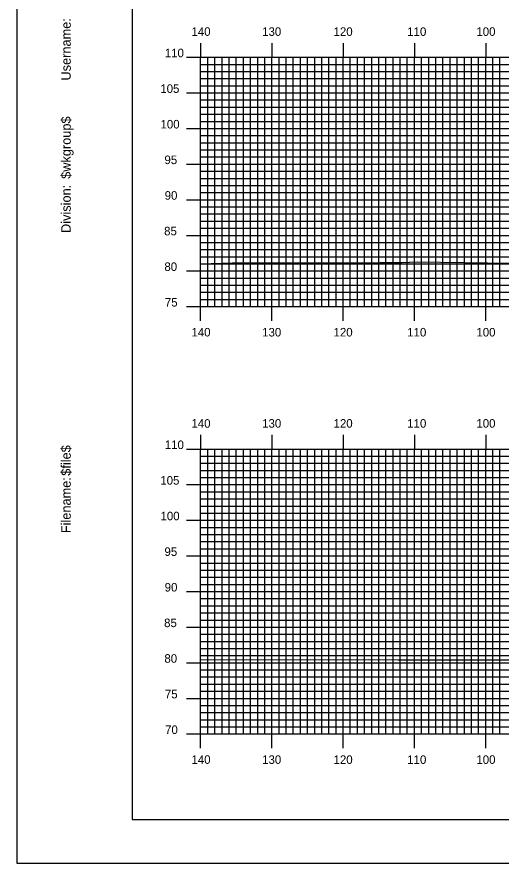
# Model space of a CAD drawing. Extents: x 1759430 to 1759773, y 442591 to 442811.
# Drawn here: x 1759429.9 to 1759497.8, y 442590.5 to 442709.3 of the extents above; entities that cross this region are included whole.
import ezdxf

# ---------------------------------------------------------------- set-up
doc = ezdxf.new("R2010")
doc.units = 0
for name, color, linetype in [('BORDER', 7, 'Continuous'), ('H_V ANNOTATION', 7, 'Continuous'), ('MAJOR', 7, 'Continuous'), ('MINOR', 7, 'Continuous'), ('PLOT BOUNDARY', 7, 'Continuous'), ('S_Roadway_Centerline', 7, 'Continuous')]:
    doc.layers.add(name, color=color, linetype=linetype)

msp = doc.modelspace()

# ---------------------------------------------------------------- linework, layer by layer
at = {"layer": 'BORDER'}
msp.add_lwpolyline([(1759446.07, 442596.67), (1759766.07, 442596.67), (1759766.07, 442806.67), (1759446.07, 442806.67)], close=True, dxfattribs=at)
at = {"layer": 'MAJOR'}
for p, q in [((1759455.67, 442705.67), (1759455.67, 442703.67)), ((1759465.67, 442705.67), (1759465.67, 442703.67)), ((1759475.67, 442705.67), (1759475.67, 442703.67)), ((1759485.67, 442705.67), (1759485.67, 442703.67)), ((1759495.67, 442705.67), (1759495.67, 442703.67)), ((1759453.67, 442703.67), (1759455.67, 442703.67)), ((1759455.67, 442703.67), (1759735.67, 442703.67)), ((1759455.67, 442668.67), (1759455.67, 442703.67)), ((1759455.67, 442668.67), (1759455.67, 442703.67)), ((1759455.67, 442703.67), (1759735.67, 442703.67)), ((1759465.67, 442668.67), (1759465.67, 442703.67)), ((1759475.67, 442668.67), (1759475.67, 442703.67)), ((1759485.67, 442668.67), (1759485.67, 442703.67)), ((1759495.67, 442668.67), (1759495.67, 442703.67)), ((1759453.67, 442698.67), (1759455.67, 442698.67)), ((1759455.67, 442698.67), (1759735.67, 442698.67)), ((1759453.67, 442693.67), (1759455.67, 442693.67)), ((1759455.67, 442693.67), (1759735.67, 442693.67)), ((1759453.67, 442688.67), (1759455.67, 442688.67)), ((1759455.67, 442688.67), (1759735.67, 442688.67)), ((1759453.67, 442683.67), (1759455.67, 442683.67)), ((1759455.67, 442683.67), (1759735.67, 442683.67)), ((1759453.67, 442678.67), (1759455.67, 442678.67)), ((1759455.67, 442678.67), (1759735.67, 442678.67)), ((1759453.67, 442673.67), (1759455.67, 442673.67)), ((1759455.67, 442673.67), (1759735.67, 442673.67)), ((1759453.67, 442668.67), (1759455.67, 442668.67)), ((1759455.67, 442668.67), (1759735.67, 442668.67)), ((1759455.67, 442668.67), (1759735.67, 442668.67)), ((1759455.67, 442666.66), (1759455.67, 442668.67)), ((1759465.67, 442666.66), (1759465.67, 442668.67)), ((1759475.67, 442666.66), (1759475.67, 442668.67)), ((1759485.67, 442666.66), (1759485.67, 442668.67)), ((1759495.67, 442666.66), (1759495.67, 442668.67)), ((1759455.67, 442650.67), (1759455.67, 442648.67)), ((1759465.67, 442650.67), (1759465.67, 442648.67)), ((1759475.67, 442650.67), (1759475.67, 442648.67)), ((1759485.67, 442650.67), (1759485.67, 442648.67)), ((1759495.67, 442650.67), (1759495.67, 442648.67)), ((1759453.67, 442648.67), (1759455.67, 442648.67)), ((1759455.67, 442648.67), (1759735.67, 442648.67)), ((1759455.67, 442608.67), (1759455.67, 442648.67)), ((1759455.67, 442608.67), (1759455.67, 442648.67)), ((1759455.67, 442648.67), (1759735.67, 442648.67)), ((1759465.67, 442608.67), (1759465.67, 442648.67)), ((1759475.67, 442608.67), (1759475.67, 442648.67)), ((1759485.67, 442608.67), (1759485.67, 442648.67)), ((1759495.67, 442608.67), (1759495.67, 442648.67)), ((1759453.67, 442643.67), (1759455.67, 442643.67)), ((1759455.67, 442643.67), (1759735.67, 442643.67)), ((1759453.67, 442638.67), (1759455.67, 442638.67)), ((1759455.67, 442638.67), (1759735.67, 442638.67)), ((1759453.67, 442633.67), (1759455.67, 442633.67)), ((1759455.67, 442633.67), (1759735.67, 442633.67)), ((1759453.67, 442628.67), (1759455.67, 442628.67)), ((1759455.67, 442628.67), (1759735.67, 442628.67)), ((1759453.67, 442623.67), (1759455.67, 442623.67)), ((1759455.67, 442623.67), (1759735.67, 442623.67)), ((1759453.67, 442618.67), (1759455.67, 442618.67)), ((1759455.67, 442618.67), (1759735.67, 442618.67)), ((1759453.67, 442613.67), (1759455.67, 442613.67)), ((1759455.67, 442613.67), (1759735.67, 442613.67)), ((1759453.67, 442608.67), (1759455.67, 442608.67)), ((1759455.67, 442608.67), (1759735.67, 442608.67)), ((1759455.67, 442608.67), (1759735.67, 442608.67)), ((1759455.67, 442606.66), (1759455.67, 442608.67)), ((1759465.67, 442606.66), (1759465.67, 442608.67)), ((1759475.67, 442606.66), (1759475.67, 442608.67)), ((1759485.67, 442606.66), (1759485.67, 442608.67)), ((1759495.67, 442606.66), (1759495.67, 442608.67))]:
    msp.add_line(p, q, dxfattribs=at)
at = {"layer": 'MINOR'}
for p, q in [((1759455.67, 442702.67), (1759735.67, 442702.67)), ((1759455.67, 442702.67), (1759457.68, 442702.67)), ((1759456.67, 442668.67), (1759456.67, 442703.67)), ((1759457.67, 442668.67), (1759457.67, 442703.67)), ((1759458.67, 442668.67), (1759458.67, 442703.67)), ((1759459.67, 442668.67), (1759459.67, 442703.67)), ((1759460.67, 442668.67), (1759460.67, 442703.67)), ((1759461.67, 442668.67), (1759461.67, 442703.67)), ((1759462.67, 442668.67), (1759462.67, 442703.67)), ((1759463.67, 442668.67), (1759463.67, 442703.67)), ((1759464.67, 442668.67), (1759464.67, 442703.67)), ((1759466.67, 442668.67), (1759466.67, 442703.67)), ((1759467.67, 442668.67), (1759467.67, 442703.67)), ((1759468.67, 442668.67), (1759468.67, 442703.67)), ((1759469.67, 442668.67), (1759469.67, 442703.67)), ((1759470.67, 442668.67), (1759470.67, 442703.67)), ((1759471.67, 442668.67), (1759471.67, 442703.67)), ((1759472.67, 442668.67), (1759472.67, 442703.67)), ((1759473.67, 442668.67), (1759473.67, 442703.67)), ((1759474.67, 442668.67), (1759474.67, 442703.67)), ((1759476.67, 442668.67), (1759476.67, 442703.67)), ((1759477.67, 442668.67), (1759477.67, 442703.67)), ((1759478.67, 442668.67), (1759478.67, 442703.67)), ((1759479.67, 442668.67), (1759479.67, 442703.67)), ((1759480.67, 442668.67), (1759480.67, 442703.67)), ((1759481.67, 442668.67), (1759481.67, 442703.67)), ((1759482.67, 442668.67), (1759482.67, 442703.67)), ((1759483.67, 442668.67), (1759483.67, 442703.67)), ((1759484.67, 442668.67), (1759484.67, 442703.67)), ((1759486.67, 442668.67), (1759486.67, 442703.67)), ((1759487.67, 442668.67), (1759487.67, 442703.67)), ((1759488.67, 442668.67), (1759488.67, 442703.67)), ((1759489.67, 442668.67), (1759489.67, 442703.67)), ((1759490.67, 442668.67), (1759490.67, 442703.67)), ((1759491.67, 442668.67), (1759491.67, 442703.67)), ((1759492.67, 442668.67), (1759492.67, 442703.67)), ((1759493.67, 442668.67), (1759493.67, 442703.67)), ((1759494.67, 442668.67), (1759494.67, 442703.67)), ((1759496.67, 442668.67), (1759496.67, 442703.67)), ((1759497.67, 442668.67), (1759497.67, 442703.67)), ((1759455.67, 442701.67), (1759735.67, 442701.67)), ((1759455.67, 442701.67), (1759457.68, 442701.67)), ((1759455.67, 442700.67), (1759735.67, 442700.67)), ((1759455.67, 442700.67), (1759457.68, 442700.67)), ((1759455.67, 442699.67), (1759735.67, 442699.67)), ((1759455.67, 442699.67), (1759457.68, 442699.67)), ((1759455.67, 442697.67), (1759735.67, 442697.67)), ((1759455.67, 442697.67), (1759457.68, 442697.67)), ((1759455.67, 442696.67), (1759735.67, 442696.67)), ((1759455.67, 442696.67), (1759457.68, 442696.67)), ((1759455.67, 442695.67), (1759735.67, 442695.67)), ((1759455.67, 442695.67), (1759457.68, 442695.67)), ((1759455.67, 442694.67), (1759735.67, 442694.67)), ((1759455.67, 442694.67), (1759457.68, 442694.67)), ((1759455.67, 442692.67), (1759735.67, 442692.67)), ((1759455.67, 442692.67), (1759457.68, 442692.67)), ((1759455.67, 442691.67), (1759735.67, 442691.67)), ((1759455.67, 442691.67), (1759457.68, 442691.67)), ((1759455.67, 442690.67), (1759735.67, 442690.67)), ((1759455.67, 442690.67), (1759457.68, 442690.67)), ((1759455.67, 442689.67), (1759735.67, 442689.67)), ((1759455.67, 442689.67), (1759457.68, 442689.67)), ((1759455.67, 442687.67), (1759735.67, 442687.67)), ((1759455.67, 442687.67), (1759457.68, 442687.67)), ((1759455.67, 442686.67), (1759735.67, 442686.67)), ((1759455.67, 442686.67), (1759457.68, 442686.67)), ((1759455.67, 442685.67), (1759735.67, 442685.67)), ((1759455.67, 442685.67), (1759457.68, 442685.67)), ((1759455.67, 442684.67), (1759735.67, 442684.67)), ((1759455.67, 442684.67), (1759457.68, 442684.67)), ((1759455.67, 442682.67), (1759735.67, 442682.67)), ((1759455.67, 442682.67), (1759457.68, 442682.67)), ((1759455.67, 442681.67), (1759735.67, 442681.67)), ((1759455.67, 442681.67), (1759457.68, 442681.67)), ((1759455.67, 442680.67), (1759735.67, 442680.67)), ((1759455.67, 442680.67), (1759457.68, 442680.67)), ((1759455.67, 442679.67), (1759735.67, 442679.67)), ((1759455.67, 442679.67), (1759457.68, 442679.67)), ((1759455.67, 442677.67), (1759735.67, 442677.67)), ((1759455.67, 442677.67), (1759457.68, 442677.67)), ((1759455.67, 442676.67), (1759735.67, 442676.67)), ((1759455.67, 442676.67), (1759457.68, 442676.67)), ((1759455.67, 442675.67), (1759735.67, 442675.67)), ((1759455.67, 442675.67), (1759457.68, 442675.67)), ((1759455.67, 442674.67), (1759735.67, 442674.67)), ((1759455.67, 442674.67), (1759457.68, 442674.67)), ((1759455.67, 442672.67), (1759735.67, 442672.67)), ((1759455.67, 442672.67), (1759457.68, 442672.67)), ((1759455.67, 442671.67), (1759735.67, 442671.67)), ((1759455.67, 442671.67), (1759457.68, 442671.67)), ((1759455.67, 442670.67), (1759735.67, 442670.67)), ((1759455.67, 442670.67), (1759457.68, 442670.67)), ((1759455.67, 442669.67), (1759735.67, 442669.67)), ((1759455.67, 442669.67), (1759457.68, 442669.67)), ((1759456.67, 442608.67), (1759456.67, 442648.67)), ((1759457.67, 442608.67), (1759457.67, 442648.67)), ((1759458.67, 442608.67), (1759458.67, 442648.67)), ((1759459.67, 442608.67), (1759459.67, 442648.67)), ((1759460.67, 442608.67), (1759460.67, 442648.67)), ((1759461.67, 442608.67), (1759461.67, 442648.67)), ((1759462.67, 442608.67), (1759462.67, 442648.67)), ((1759463.67, 442608.67), (1759463.67, 442648.67)), ((1759464.67, 442608.67), (1759464.67, 442648.67)), ((1759466.67, 442608.67), (1759466.67, 442648.67)), ((1759467.67, 442608.67), (1759467.67, 442648.67)), ((1759468.67, 442608.67), (1759468.67, 442648.67)), ((1759469.67, 442608.67), (1759469.67, 442648.67)), ((1759470.67, 442608.67), (1759470.67, 442648.67)), ((1759471.67, 442608.67), (1759471.67, 442648.67)), ((1759472.67, 442608.67), (1759472.67, 442648.67)), ((1759473.67, 442608.67), (1759473.67, 442648.67)), ((1759474.67, 442608.67), (1759474.67, 442648.67)), ((1759476.67, 442608.67), (1759476.67, 442648.67)), ((1759477.67, 442608.67), (1759477.67, 442648.67)), ((1759478.67, 442608.67), (1759478.67, 442648.67)), ((1759479.67, 442608.67), (1759479.67, 442648.67)), ((1759480.67, 442608.67), (1759480.67, 442648.67)), ((1759481.67, 442608.67), (1759481.67, 442648.67)), ((1759482.67, 442608.67), (1759482.67, 442648.67)), ((1759483.67, 442608.67), (1759483.67, 442648.67)), ((1759484.67, 442608.67), (1759484.67, 442648.67)), ((1759486.67, 442608.67), (1759486.67, 442648.67)), ((1759487.67, 442608.67), (1759487.67, 442648.67)), ((1759488.67, 442608.67), (1759488.67, 442648.67)), ((1759489.67, 442608.67), (1759489.67, 442648.67)), ((1759490.67, 442608.67), (1759490.67, 442648.67)), ((1759491.67, 442608.67), (1759491.67, 442648.67)), ((1759492.67, 442608.67), (1759492.67, 442648.67)), ((1759493.67, 442608.67), (1759493.67, 442648.67)), ((1759494.67, 442608.67), (1759494.67, 442648.67)), ((1759496.67, 442608.67), (1759496.67, 442648.67)), ((1759497.67, 442608.67), (1759497.67, 442648.67)), ((1759455.67, 442647.67), (1759735.67, 442647.67)), ((1759455.67, 442647.67), (1759457.68, 442647.67)), ((1759455.67, 442646.67), (1759735.67, 442646.67)), ((1759455.67, 442646.67), (1759457.68, 442646.67)), ((1759455.67, 442645.67), (1759735.67, 442645.67)), ((1759455.67, 442645.67), (1759457.68, 442645.67)), ((1759455.67, 442644.67), (1759735.67, 442644.67)), ((1759455.67, 442644.67), (1759457.68, 442644.67)), ((1759455.67, 442642.67), (1759735.67, 442642.67)), ((1759455.67, 442642.67), (1759457.68, 442642.67)), ((1759455.67, 442641.67), (1759735.67, 442641.67)), ((1759455.67, 442641.67), (1759457.68, 442641.67)), ((1759455.67, 442640.67), (1759735.67, 442640.67)), ((1759455.67, 442640.67), (1759457.68, 442640.67)), ((1759455.67, 442639.67), (1759735.67, 442639.67)), ((1759455.67, 442639.67), (1759457.68, 442639.67)), ((1759455.67, 442637.67), (1759735.67, 442637.67)), ((1759455.67, 442637.67), (1759457.68, 442637.67)), ((1759455.67, 442636.67), (1759735.67, 442636.67)), ((1759455.67, 442636.67), (1759457.68, 442636.67)), ((1759455.67, 442635.67), (1759735.67, 442635.67)), ((1759455.67, 442635.67), (1759457.68, 442635.67)), ((1759455.67, 442634.67), (1759735.67, 442634.67)), ((1759455.67, 442634.67), (1759457.68, 442634.67)), ((1759455.67, 442632.67), (1759735.67, 442632.67)), ((1759455.67, 442632.67), (1759457.68, 442632.67)), ((1759455.67, 442631.67), (1759735.67, 442631.67)), ((1759455.67, 442631.67), (1759457.68, 442631.67)), ((1759455.67, 442630.67), (1759735.67, 442630.67)), ((1759455.67, 442630.67), (1759457.68, 442630.67)), ((1759455.67, 442629.67), (1759735.67, 442629.67)), ((1759455.67, 442629.67), (1759457.68, 442629.67)), ((1759455.67, 442627.67), (1759735.67, 442627.67)), ((1759455.67, 442627.67), (1759457.68, 442627.67)), ((1759455.67, 442626.67), (1759735.67, 442626.67)), ((1759455.67, 442626.67), (1759457.68, 442626.67)), ((1759455.67, 442625.67), (1759735.67, 442625.67)), ((1759455.67, 442625.67), (1759457.68, 442625.67)), ((1759455.67, 442624.67), (1759735.67, 442624.67)), ((1759455.67, 442624.67), (1759457.68, 442624.67)), ((1759455.67, 442622.67), (1759735.67, 442622.67)), ((1759455.67, 442622.67), (1759457.68, 442622.67)), ((1759455.67, 442621.67), (1759735.67, 442621.67)), ((1759455.67, 442621.67), (1759457.68, 442621.67)), ((1759455.67, 442620.67), (1759735.67, 442620.67)), ((1759455.67, 442620.67), (1759457.68, 442620.67)), ((1759455.67, 442619.67), (1759735.67, 442619.67)), ((1759455.67, 442619.67), (1759457.68, 442619.67)), ((1759455.67, 442617.67), (1759735.67, 442617.67)), ((1759455.67, 442617.67), (1759457.68, 442617.67)), ((1759455.67, 442616.67), (1759735.67, 442616.67)), ((1759455.67, 442616.67), (1759457.68, 442616.67)), ((1759455.67, 442615.67), (1759735.67, 442615.67)), ((1759455.67, 442615.67), (1759457.68, 442615.67)), ((1759455.67, 442614.67), (1759735.67, 442614.67)), ((1759455.67, 442614.67), (1759457.68, 442614.67)), ((1759455.67, 442612.67), (1759735.67, 442612.67)), ((1759455.67, 442612.67), (1759457.68, 442612.67)), ((1759455.67, 442611.67), (1759735.67, 442611.67)), ((1759455.67, 442611.67), (1759457.68, 442611.67)), ((1759455.67, 442610.67), (1759735.67, 442610.67)), ((1759455.67, 442610.67), (1759457.68, 442610.67)), ((1759455.67, 442609.67), (1759735.67, 442609.67)), ((1759455.67, 442609.67), (1759457.68, 442609.67))]:
    msp.add_line(p, q, dxfattribs=at)
at = {"layer": 'PLOT BOUNDARY'}
msp.add_lwpolyline([(1759429.89, 442590.55), (1759769.89, 442590.55), (1759769.89, 442810.55), (1759429.89, 442810.55)], close=True, dxfattribs=at)
at = {"layer": 'S_Roadway_Centerline'}
for points in [[(1759455.67, 442674.66), (1759461.59, 442674.85), (1759467.75, 442674.83), (1759480.85, 442674.86), (1759483.88, 442674.88), (1759486.06, 442674.93), (1759505.83, 442674.67), (1759508.01, 442674.65), (1759508.44, 442674.64), (1759530.15, 442674.94), (1759531.73, 442674.91), (1759531.98, 442675.01), (1759532.23, 442674.94), (1759536.65, 442675.05), (1759556.12, 442675.12), (1759564.25, 442675.3), (1759567.34, 442675.32)], [(1759455.67, 442619.06), (1759479.21, 442619.13), (1759483.37, 442619.07), (1759501.67, 442619.08), (1759513.32, 442619.4), (1759528.25, 442619.39), (1759534.62, 442619.59), (1759541.74, 442619.62), (1759546.6, 442619.49), (1759547.37, 442619.52), (1759548.69, 442620.13), (1759549.27, 442620), (1759550.6, 442619.56), (1759550.76, 442619.53), (1759550.97, 442619.36), (1759551.43, 442619.21), (1759553.34, 442619.05), (1759553.96, 442618.69), (1759556.06, 442618.61), (1759561.87, 442618.6), (1759576.31, 442619.17)]]:
    msp.add_lwpolyline(points, dxfattribs=at)

# ---------------------------------------------------------------- texts
at = {"layer": 'BORDER'}
for s, p in [('Username:', (1759437.44, 442700.4)), ('Username:', (1759437.44, 442700.4)), ('$wkgroup$', (1759437.44, 442686.6)), ('$wkgroup$', (1759437.44, 442686.6)), ('Division:', (1759437.44, 442679)), ('Division:', (1759437.44, 442679)), ('$file$', (1759437.44, 442644.92)), ('$file$', (1759437.44, 442644.92)), ('Filename:', (1759437.44, 442636.86)), ('Filename:', (1759437.44, 442636.86))]:
    msp.add_text(s, height=1.339, rotation=90, dxfattribs=at).set_placement(p)
at = {"layer": 'H_V ANNOTATION'}
for s, p in [('140', (1759454.38, 442706.67)), ('130', (1759464.3, 442706.67)), ('120', (1759474.32, 442706.67)), ('110', (1759484.66, 442706.67)), ('100', (1759494.36, 442706.67)), ('110', (1759450.64, 442703.67)), ('105', (1759450.01, 442698.67)), ('100', (1759450.04, 442693.67)), ('95', (1759450.59, 442688.67)), ('90', (1759450.62, 442683.67)), ('85', (1759450.54, 442678.67)), ('80', (1759450.58, 442673.67)), ('75', (1759450.65, 442668.67)), ('140', (1759454.38, 442664.47)), ('130', (1759464.3, 442664.47)), ('120', (1759474.32, 442664.47)), ('110', (1759484.66, 442664.47)), ('100', (1759494.36, 442664.47)), ('140', (1759454.38, 442651.67)), ('130', (1759464.3, 442651.67)), ('120', (1759474.32, 442651.67)), ('110', (1759484.66, 442651.67)), ('100', (1759494.36, 442651.67)), ('110', (1759450.64, 442648.67)), ('105', (1759450.01, 442643.67)), ('100', (1759450.04, 442638.67)), ('95', (1759450.59, 442633.67)), ('90', (1759450.62, 442628.67)), ('85', (1759450.54, 442623.67)), ('80', (1759450.58, 442618.67)), ('75', (1759450.65, 442613.67)), ('70', (1759450.68, 442608.67)), ('140', (1759454.38, 442604.47)), ('130', (1759464.3, 442604.47)), ('120', (1759474.32, 442604.47)), ('110', (1759484.66, 442604.47)), ('100', (1759494.36, 442604.47))]:
    msp.add_text(s, height=1.2, dxfattribs=at).set_placement(p)
at = {"layer": 'MAJOR'}
for p in [(1759455.67, 442668.67), (1759455.67, 442608.67)]:
    msp.add_text('-', height=0.012, dxfattribs=at).set_placement(p)

doc.saveas('drawing.dxf')
